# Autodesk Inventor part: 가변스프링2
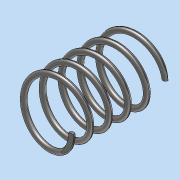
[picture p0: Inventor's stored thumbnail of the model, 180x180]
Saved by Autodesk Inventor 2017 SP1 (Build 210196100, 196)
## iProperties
Part Number: 가변스프링2
Material: 강철, 연강
Document SubType Name: Modeling
Designer: MRC
Density: 7.85 g/cm^3
Appearance: 반연마
Mass: 8.42324 g
Surface Area: 21.7217 cm^2
Volume: 1.07302 cm^3
Author: MRC
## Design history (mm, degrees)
sketch "스케치1"
  geometry: L1 (0, 0)-(0, 36.411); L2 (0, 36.411)-(11, 36.411); L3 (0, 0)-(11, 0); C1 r 1 at (11, 0)
  constraints: 6 end point, 2 horizontal, 1 centre point, 1 coincident, 1 vertical
  dimensions: "d0" = 36.4112 distance of L1.start L1.end (derived); "d1" = 11 distance of L1.end L2.end; "d2" = 22 diameter of L3.end L1; "d3" = 2 diameter of C1
feature "코일1" sketch "스케치1" pitch "d4" = 10; turns "d6" = 5; dims "d5" = 36.4112 (= d0), "d7" = 0, angle "d8" = 90 deg, angle "d9" = 90 deg, "d10" = 0, "d11" = 0
sketch "스케치2"
  geometry: L1 (36.411, 20)-(0, 20); L2 (0, 20)-(0, -20); L3 (0, -20)-(36.411, -20); L4 (36.411, -20)-(36.411, 20); 2 further points
  constraints: 8 end point, 2 parallel, 1 coincident, 1 horizontal, 1 midpoint, 1 perpendicular
  dimensions: "d12" = 36.4112 distance of L2.end L3.end (= d0); "d13" = 40 distance of L3.end L1.start
extrude "돌출1" sketch "스케치2" stored distance "d14" = 0; taper "d15" = 0 deg
node "솔리드1"
